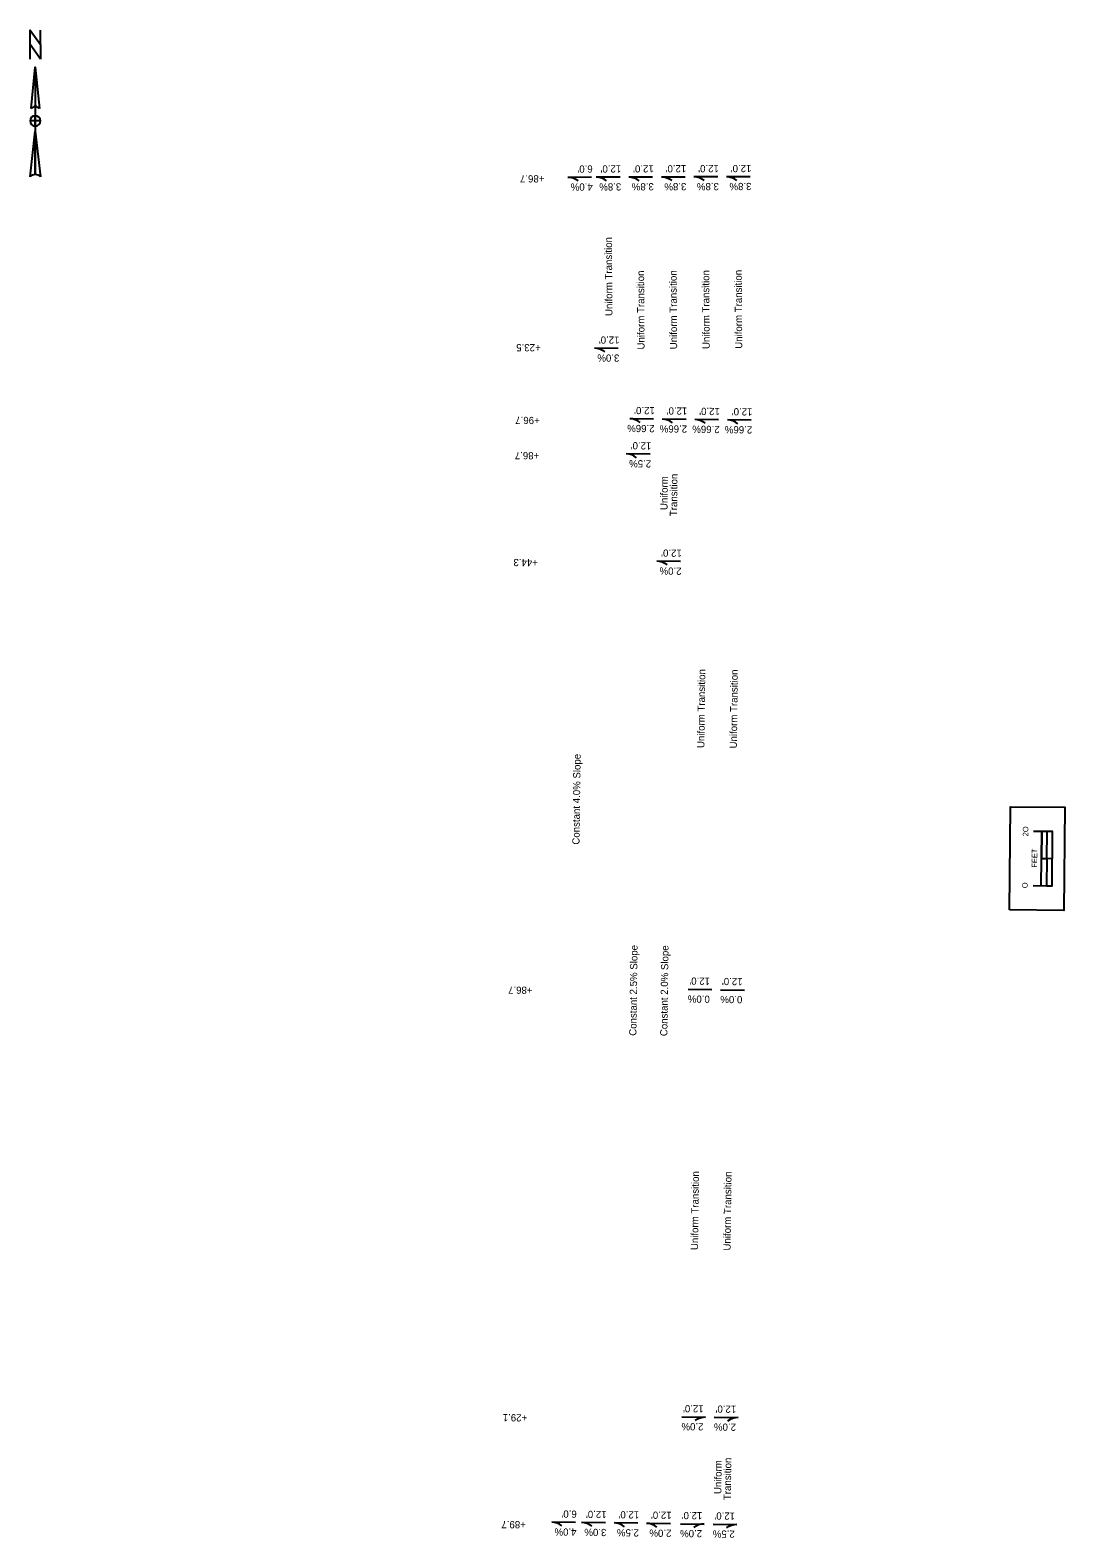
# Model space of a CAD drawing. Extents: x 20505195 to 20506806, y 7965197 to 7979043.
# Drawn here: x 20506425 to 20506806, y 7972886 to 7973442 of the extents above; entities that cross this region are included whole.
import ezdxf

# ---------------------------------------------------------------- set-up
doc = ezdxf.new("R2010")
doc.units = 0
doc.layers.add('Cell', color=7, linetype='Continuous')
doc.layers.add('SheetText', color=7, linetype='Continuous')

msp = doc.modelspace()

# ---------------------------------------------------------------- linework, layer by layer
at = {"layer": 'Cell'}
for p, q in [((20506426.44, 7973428.25), (20506427.96, 7973413.04)), ((20506426.44, 7973428.25), (20506426.44, 7973388.7)), ((20506424.92, 7973413.04), (20506424.92, 7973413.04)), ((20506424.98, 7973413.18), (20506425.26, 7973413.5)), ((20506426.44, 7973406.58), (20506426.44, 7973406.58)), ((20506424.54, 7973387.94), (20506426.44, 7973404.68))]:
    msp.add_line(p, q, dxfattribs=at)
msp.add_lwpolyline([(20506428.34, 7973431.3), (20506424.54, 7973436.62), (20506424.54, 7973441.94), (20506428.34, 7973436.62)], close=True, dxfattribs=at)
for points in [[(20506424.54, 7973431.3), (20506424.54, 7973441.94), (20506428.34, 7973436.62), (20506428.34, 7973441.94)], [(20506424.92, 7973413.04), (20506426.44, 7973428.25), (20506426.44, 7973413.8)], [(20506426.44, 7973406.58), (20506426.44, 7973408.48), (20506424.54, 7973408.48)], [(20506428.34, 7973408.48), (20506426.44, 7973408.48), (20506426.44, 7973410.38)], [(20506426.44, 7973388.7), (20506426.44, 7973404.68), (20506428.34, 7973387.94)]]:
    msp.add_lwpolyline(points, dxfattribs=at)
for centre, radius, start, end in [((20506426.44, 7973411.9), 1.9, 90.0204, 143.1257), ((20506426.44, 7973411.9), 1.9, 36.8481, 90.0218), ((20506426.44, 7973408.48), 1.9, 90, 180), ((20506426.44, 7973408.48), 1.9, 180, 270), ((20506426.44, 7973408.48), 1.9, 0, 90), ((20506426.44, 7973408.48), 1.9, 270, 360), ((20506426.44, 7973385.95), 2.76, 89.9894, 133.619), ((20506426.44, 7973385.94), 2.76, 46.4021, 90.0006)]:
    msp.add_arc(centre, radius, start, end, dxfattribs=at)
at = {"layer": 'SheetText'}
for p, q in [((20506631.5, 7973387.72), (20506622.73, 7973387.69)), ((20506642.01, 7973387.75), (20506633.24, 7973387.72)), ((20506654.01, 7973387.79), (20506645.24, 7973387.76)), ((20506666.01, 7973387.82), (20506657.24, 7973387.8)), ((20506678.01, 7973387.86), (20506669.24, 7973387.83)), ((20506690.01, 7973387.9), (20506681.24, 7973387.87)), ((20506641.35, 7973324.64), (20506632.58, 7973324.71)), ((20506654.35, 7973298.63), (20506645.58, 7973298.74)), ((20506666.35, 7973298.48), (20506657.58, 7973298.59)), ((20506678.35, 7973298.33), (20506669.58, 7973298.44)), ((20506690.35, 7973298.18), (20506681.58, 7973298.29)), ((20506653.08, 7973285.65), (20506644.31, 7973285.76)), ((20506664.3, 7973246.1), (20506655.53, 7973246.21)), ((20506801.36, 7973136.59), (20506797.36, 7973136.63)), ((20506801.36, 7973136.59), (20506797.36, 7973136.63)), ((20506667.07, 7973088.45), (20506675.84, 7973088.34)), ((20506679.07, 7973088.3), (20506687.84, 7973088.19)), ((20506664.73, 7972930.87), (20506673.5, 7972930.76)), ((20506676.72, 7972930.72), (20506685.49, 7972930.61)), ((20506625.57, 7972891.96), (20506616.8, 7972892.07)), ((20506636.58, 7972891.82), (20506627.81, 7972891.93)), ((20506648.58, 7972891.67), (20506639.81, 7972891.78)), ((20506660.55, 7972891.52), (20506651.78, 7972891.63)), ((20506664.23, 7972891.47), (20506673, 7972891.36)), ((20506676.29, 7972891.32), (20506685.06, 7972891.21))]:
    msp.add_line(p, q, dxfattribs=at)
for points in [[(20506785.55, 7973117.76), (20506785.98, 7973155.76), (20506805.98, 7973155.53), (20506805.55, 7973117.54)], [(20506785.55, 7973117.76), (20506785.98, 7973155.76), (20506805.98, 7973155.53), (20506805.55, 7973117.54)], [(20506799.35, 7973136.61), (20506799.46, 7973146.61), (20506797.48, 7973146.63), (20506797.36, 7973136.63)], [(20506801.25, 7973126.59), (20506801.36, 7973136.59), (20506799.35, 7973136.61), (20506799.24, 7973126.61)]]:
    msp.add_lwpolyline(points, close=True, dxfattribs=at)
for points in [[(20506794.25, 7973126.66), (20506801.25, 7973126.59), (20506801.48, 7973146.58), (20506794.48, 7973146.66)], [(20506797.25, 7973126.63), (20506797.48, 7973146.63)]]:
    msp.add_lwpolyline(points, dxfattribs=at)
for centre, start, end in [((20506622.75, 7973381.53), 51.9728, 90.1758), ((20506633.26, 7973381.56), 51.9728, 90.1758), ((20506645.26, 7973381.59), 51.9728, 90.1758), ((20506657.26, 7973381.63), 51.9728, 90.1758), ((20506669.26, 7973381.67), 51.9728, 90.1758), ((20506681.26, 7973381.7), 51.9728, 90.1758), ((20506632.53, 7973318.55), 51.3343, 89.5373), ((20506645.5, 7973292.58), 51.076, 89.2791), ((20506657.5, 7973292.43), 51.076, 89.2791), ((20506669.5, 7973292.27), 51.076, 89.2791), ((20506681.5, 7973292.12), 51.076, 89.2791), ((20506644.24, 7973279.59), 51.076, 89.2791), ((20506655.46, 7973240.05), 51.076, 89.2791), ((20506673.42, 7972924.6), 89.2791, 127.4821), ((20506685.42, 7972924.45), 89.2791, 127.4821), ((20506616.72, 7972885.91), 51.076, 89.2791), ((20506627.74, 7972885.77), 51.076, 89.2791), ((20506639.73, 7972885.62), 51.076, 89.2791), ((20506651.7, 7972885.47), 51.076, 89.2791), ((20506672.92, 7972885.2), 89.2791, 127.4821), ((20506684.99, 7972885.05), 89.2791, 127.4821)]:
    msp.add_arc(centre, 6.16, start, end, dxfattribs=at)

# ---------------------------------------------------------------- texts
for s, height, rotation, p in [("6.0'", 2.664, 180.2786, (20506631.92, 7973392.11)), ("12.0'", 2.664, 180.2786, (20506642.43, 7973392.15)), ("12.0'", 2.664, 180.2786, (20506654.43, 7973392.18)), ("12.0'", 2.664, 180.2786, (20506666.43, 7973392.22)), ("12.0'", 2.664, 180.2786, (20506678.43, 7973392.26)), ("12.0'", 2.664, 180.2786, (20506690.43, 7973392.29)), ('+86.7', 2.664, 180.1758, (20506614.12, 7973388.49)), ('4.0%', 2.664, 180.2786, (20506631.94, 7973385.49)), ('3.8%', 2.664, 180.2786, (20506642.45, 7973385.52)), ('3.8%', 2.664, 180.2786, (20506654.45, 7973385.56)), ('3.8%', 2.664, 180.2786, (20506666.45, 7973385.59)), ('3.8%', 2.664, 180.2786, (20506678.45, 7973385.63)), ('3.8%', 2.664, 180.2786, (20506690.45, 7973385.67)), ('Uniform Transition', 2.664, 90.3784, (20506639.2, 7973336.6)), ('Uniform Transition', 2.664, 90.3784, (20506651.05, 7973324.26)), ('Uniform Transition', 2.664, 90.3784, (20506663.05, 7973324.35)), ('Uniform Transition', 2.664, 90.3784, (20506675.05, 7973324.43)), ('Uniform Transition', 2.664, 90.3784, (20506687.05, 7973324.52)), ("12.0'", 2.664, 179.64, (20506641.82, 7973329.03)), ('+23.5', 2.664, 179.64, (20506612.75, 7973326.21)), ('3.0%', 2.664, 179.64, (20506641.76, 7973322.41)), ("12.0'", 2.664, 179.3818, (20506654.84, 7973303.02)), ("12.0'", 2.664, 179.3818, (20506666.83, 7973302.87)), ("12.0'", 2.664, 179.3818, (20506678.83, 7973302.72)), ("12.0'", 2.664, 179.3818, (20506690.83, 7973302.57)), ('+96.7', 2.664, 179.3818, (20506612.4, 7973299.39)), ('2.66%', 2.664, 179.3818, (20506654.75, 7973296.4)), ('2.66%', 2.664, 179.3818, (20506666.75, 7973296.24)), ('2.66%', 2.664, 179.3818, (20506678.75, 7973296.09)), ('2.66%', 2.664, 179.3818, (20506690.75, 7973295.94)), ("12.0'", 2.664, 179.3818, (20506653.57, 7973290.04)), ('+86.7', 2.664, 179.3818, (20506612.23, 7973286.39)), ('2.5%', 2.664, 179.3818, (20506653.48, 7973283.41)), ('Uniform', 2.664, 89.2905, (20506659.49, 7973265.06)), ('Transition', 2.664, 89.2905, (20506663, 7973262.82)), ('+44.3', 2.664, 179.3818, (20506611.74, 7973246.99)), ("12.0'", 2.664, 179.3818, (20506664.79, 7973250.49)), ('2.0%', 2.664, 179.3818, (20506664.7, 7973243.87)), ('Uniform Transition', 2.664, 89.2905, (20506673.08, 7973177.35)), ('Uniform Transition', 2.664, 89.2905, (20506685.07, 7973177.2)), ('Constant 4.0% Slope', 2.664, 89.2393, (20506627.05, 7973141.75)), ('2O', 2, 89.3531, (20506792.46, 7973144.81)), ('FEET', 2, 89.3531, (20506795.73, 7973133.26)), ('O', 2, 89.3531, (20506792.24, 7973125.7)), ('Constant 2.5% Slope', 2.664, 89.2393, (20506648.03, 7973071.31)), ('Constant 2.0% Slope', 2.664, 89.2393, (20506659.44, 7973071.17)), ("12.0'", 2.664, 179.3818, (20506675.19, 7973092.75)), ("12.0'", 2.664, 179.3818, (20506687.19, 7973092.6)), ('+86.7', 2.664, 179.3818, (20506609.76, 7973089.4)), ('0.0%', 2.664, 179.3818, (20506675.11, 7973086.12)), ('0.0%', 2.664, 179.3818, (20506687.1, 7973085.97)), ('Uniform Transition', 2.664, 89.2905, (20506670.75, 7972992.32)), ('Uniform Transition', 2.664, 89.2905, (20506682.75, 7972992.17)), ("12.0'", 2.664, 179.3818, (20506672.85, 7972935.16)), ("12.0'", 2.664, 179.3818, (20506684.85, 7972935.01)), ('+29.1', 2.664, 179.3818, (20506607.79, 7972931.82)), ('2.0%', 2.664, 179.3818, (20506672.77, 7972928.54)), ('2.0%', 2.664, 179.3818, (20506684.76, 7972928.39)), ('Uniform', 2.664, 89.2905, (20506679.33, 7972902.42)), ('Transition', 2.664, 89.2905, (20506682.84, 7972900.19)), ("6.0'", 2.664, 179.3818, (20506626.06, 7972896.35)), ("12.0'", 2.664, 179.3818, (20506637.07, 7972896.21)), ("12.0'", 2.664, 179.3818, (20506649.07, 7972896.06)), ("12.0'", 2.664, 179.3818, (20506661.03, 7972895.91)), ("12.0'", 2.664, 179.3818, (20506672.36, 7972895.77)), ("12.0'", 2.664, 179.3818, (20506684.42, 7972895.62)), ('+89.7', 2.664, 179.3818, (20506607.28, 7972892.42)), ('4.0%', 2.664, 179.3818, (20506625.97, 7972889.73)), ('3.0%', 2.664, 179.3818, (20506636.98, 7972889.59)), ('2.5%', 2.664, 179.3818, (20506648.98, 7972889.44)), ('2.0%', 2.664, 179.3818, (20506660.95, 7972889.29)), ('2.0%', 2.664, 179.3818, (20506672.27, 7972889.14)), ('2.5%', 2.664, 179.3818, (20506684.33, 7972888.99))]:
    msp.add_text(s, height=height, rotation=rotation, dxfattribs=at).set_placement(p)

doc.saveas('drawing.dxf')
